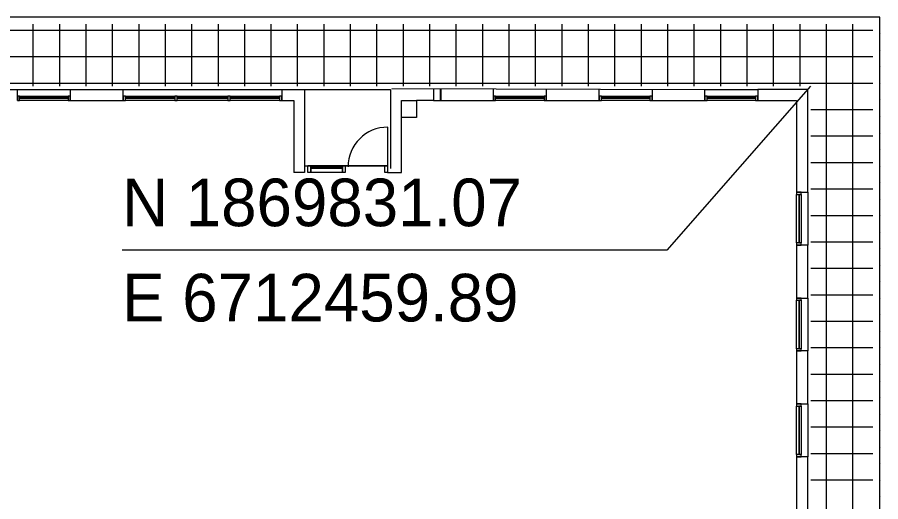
# Model space of a CAD drawing. Extents: x 6712138 to 6712574, y 1869536 to 1870160.
# Drawn here: x 6712399.9 to 6712465.2, y 1869799.7 to 1869836.3 of the extents above; entities that cross this region are included whole.
import ezdxf

# ---------------------------------------------------------------- set-up
doc = ezdxf.new("R2010")
doc.units = 0
for name, color, linetype in [('A-DETL-MBND', 7, 'Continuous'), ('A-FLOR-OTLN', 7, 'Continuous'), ('A-FLOR-PATT', 7, 'Continuous'), ('A-GLAZ', 7, 'Continuous'), ('A-GLAZ-CWMG', 7, 'Continuous'), ('A-GLAZ-FRAM', 7, 'Continuous'), ('A-WALL-FULL-EXT', 7, 'Continuous'), ('I-WALL', 7, 'Continuous')]:
    doc.layers.add(name, color=color, linetype=linetype)

# ---------------------------------------------------------------- blocks, each defined once
blk = doc.blocks.new('Curtain Wall Sgl Glass-WideStiles-PH - Curtain Wall Sgl Glass-187-xAFP01')
at = {"layer": 'A-DETL-MBND'}
blk.add_line((0.0762, 0.0085), (0.0762, 0.1609), dxfattribs=at)
blk.add_arc((0.0762, 0.0085), 0.1524, 90, 180, dxfattribs=at)

msp = doc.modelspace()

# ---------------------------------------------------------------- linework, layer by layer
at = {"layer": 'A-FLOR-OTLN'}
for p, q in [((6712421.62, 1869830.833), (6712428.131, 1869830.833)), ((6712431.391, 1869830.76), (6712431.402, 1869830.76)), ((6712431.933, 1869830.76), (6712431.912, 1869830.76)), ((6712431.391, 1869829.989), (6712431.402, 1869829.989)), ((6712431.912, 1869829.989), (6712431.933, 1869829.989)), ((6712421.62, 1869825.052), (6712427.911, 1869825.052)), ((6712421.891, 1869825.073), (6712427.89, 1869825.073)), ((6712427.89, 1869825.073), (6712427.89, 1869825.098))]:
    msp.add_line(p, q, dxfattribs=at)
msp.add_lwpolyline([(6712463.745, 1869723.291), (6712465.141, 1869723.291), (6712465.141, 1869836.281), (6712254.683, 1869836.281)], dxfattribs=at)
at = {"layer": 'A-FLOR-PATT'}
for p, q in [((6712464.62, 1869835.281), (6712255.204, 1869835.281)), ((6712401.11, 1869831.073), (6712401.11, 1869835.76)), ((6712403.11, 1869831.073), (6712403.11, 1869835.76)), ((6712405.11, 1869831.073), (6712405.11, 1869835.76)), ((6712407.11, 1869831.073), (6712407.11, 1869835.76)), ((6712409.11, 1869831.073), (6712409.11, 1869835.76)), ((6712411.11, 1869831.073), (6712411.11, 1869835.76)), ((6712413.11, 1869831.073), (6712413.11, 1869835.76)), ((6712415.11, 1869831.073), (6712415.11, 1869835.76)), ((6712417.11, 1869831.073), (6712417.11, 1869835.76)), ((6712419.11, 1869831.073), (6712419.11, 1869835.76)), ((6712421.11, 1869831.073), (6712421.11, 1869835.76)), ((6712423.11, 1869831.073), (6712423.11, 1869835.76)), ((6712425.11, 1869831.073), (6712425.11, 1869835.76)), ((6712427.11, 1869831.073), (6712427.11, 1869835.76)), ((6712429.11, 1869831.073), (6712429.11, 1869835.76)), ((6712431.11, 1869831.073), (6712431.11, 1869835.76)), ((6712433.11, 1869831.073), (6712433.11, 1869835.76)), ((6712435.11, 1869831.073), (6712435.11, 1869835.76)), ((6712437.11, 1869831.073), (6712437.11, 1869835.76)), ((6712439.11, 1869831.073), (6712439.11, 1869835.76)), ((6712441.11, 1869831.073), (6712441.11, 1869835.76)), ((6712443.11, 1869831.073), (6712443.11, 1869835.76)), ((6712445.11, 1869831.073), (6712445.11, 1869835.76)), ((6712447.11, 1869831.073), (6712447.11, 1869835.76)), ((6712449.11, 1869831.073), (6712449.11, 1869835.76)), ((6712451.11, 1869831.073), (6712451.11, 1869835.76)), ((6712453.11, 1869831.073), (6712453.11, 1869835.76)), ((6712455.11, 1869831.073), (6712455.11, 1869835.76)), ((6712457.11, 1869831.073), (6712457.11, 1869835.76)), ((6712459.11, 1869831.073), (6712459.11, 1869835.76)), ((6712461.11, 1869759.073), (6712461.11, 1869835.76)), ((6712463.11, 1869759.073), (6712463.11, 1869835.76)), ((6712465.212, 1869835.032), (6712465.212, 1869835.032)), ((6712465.212, 1869833.782), (6712465.212, 1869833.782)), ((6712464.62, 1869833.281), (6712255.204, 1869833.281)), ((6712465.212, 1869832.532), (6712465.212, 1869832.532)), ((6712464.619, 1869831.281), (6712255.204, 1869831.281)), ((6712465.212, 1869831.282), (6712465.212, 1869831.282)), ((6712465.212, 1869830.032), (6712465.212, 1869830.032)), ((6712464.618, 1869829.281), (6712459.933, 1869829.281)), ((6712465.212, 1869828.782), (6712465.212, 1869828.782)), ((6712465.212, 1869827.532), (6712465.212, 1869827.532)), ((6712464.618, 1869827.281), (6712459.933, 1869827.281)), ((6712465.212, 1869826.282), (6712465.212, 1869826.282)), ((6712464.617, 1869825.281), (6712459.933, 1869825.281)), ((6712465.212, 1869825.032), (6712465.212, 1869825.032)), ((6712465.212, 1869823.782), (6712465.212, 1869823.782)), ((6712464.617, 1869823.281), (6712459.933, 1869823.281)), ((6712465.212, 1869822.532), (6712465.212, 1869822.532)), ((6712464.616, 1869821.281), (6712459.933, 1869821.281)), ((6712465.212, 1869821.282), (6712465.212, 1869821.282)), ((6712465.212, 1869820.032), (6712465.212, 1869820.032)), ((6712464.616, 1869819.281), (6712459.933, 1869819.281)), ((6712465.212, 1869818.782), (6712465.212, 1869818.782)), ((6712464.615, 1869817.281), (6712459.933, 1869817.281)), ((6712465.212, 1869817.532), (6712465.212, 1869817.532)), ((6712465.212, 1869816.282), (6712465.212, 1869816.282)), ((6712464.614, 1869815.281), (6712459.933, 1869815.281)), ((6712465.212, 1869815.032), (6712465.212, 1869815.032)), ((6712465.212, 1869813.782), (6712465.212, 1869813.782)), ((6712464.614, 1869813.281), (6712459.933, 1869813.281)), ((6712465.212, 1869812.532), (6712465.212, 1869812.532)), ((6712464.613, 1869811.281), (6712459.933, 1869811.281)), ((6712465.212, 1869811.282), (6712465.212, 1869811.282)), ((6712465.212, 1869810.032), (6712465.212, 1869810.032)), ((6712464.613, 1869809.281), (6712459.933, 1869809.281)), ((6712465.212, 1869808.782), (6712465.212, 1869808.782)), ((6712464.612, 1869807.281), (6712459.933, 1869807.281)), ((6712465.212, 1869807.532), (6712465.212, 1869807.532)), ((6712465.212, 1869806.282), (6712465.212, 1869806.282)), ((6712464.612, 1869805.281), (6712459.933, 1869805.281)), ((6712465.212, 1869805.032), (6712465.212, 1869805.032)), ((6712464.611, 1869803.281), (6712459.933, 1869803.281)), ((6712465.212, 1869803.782), (6712465.212, 1869803.782)), ((6712465.212, 1869802.532), (6712465.212, 1869802.532)), ((6712464.611, 1869801.281), (6712459.933, 1869801.281)), ((6712465.212, 1869801.282), (6712465.212, 1869801.282)), ((6712465.212, 1869800.032), (6712465.212, 1869800.032))]:
    msp.add_line(p, q, dxfattribs=at)
at = {"layer": 'A-GLAZ'}
for p, q in [((6712400.079, 1869830.219), (6712400.079, 1869830.156)), ((6712403.745, 1869830.219), (6712400.079, 1869830.219)), ((6712400.079, 1869830.156), (6712403.745, 1869830.156)), ((6712403.745, 1869830.156), (6712403.745, 1869830.219)), ((6712411.829, 1869830.219), (6712408.079, 1869830.219)), ((6712408.079, 1869830.219), (6712408.079, 1869830.156)), ((6712408.079, 1869830.156), (6712411.829, 1869830.156)), ((6712411.829, 1869830.156), (6712411.829, 1869830.219)), ((6712415.829, 1869830.219), (6712411.995, 1869830.219)), ((6712411.995, 1869830.219), (6712411.995, 1869830.156)), ((6712411.995, 1869830.156), (6712415.829, 1869830.156)), ((6712415.829, 1869830.156), (6712415.829, 1869830.219)), ((6712419.745, 1869830.219), (6712415.995, 1869830.219)), ((6712415.995, 1869830.219), (6712415.995, 1869830.156)), ((6712415.995, 1869830.156), (6712419.745, 1869830.156)), ((6712419.745, 1869830.156), (6712419.745, 1869830.219)), ((6712436.079, 1869830.219), (6712436.079, 1869830.156)), ((6712439.745, 1869830.219), (6712436.079, 1869830.219)), ((6712436.079, 1869830.156), (6712439.745, 1869830.156)), ((6712439.745, 1869830.156), (6712439.745, 1869830.219)), ((6712444.079, 1869830.219), (6712444.079, 1869830.156)), ((6712447.745, 1869830.219), (6712444.079, 1869830.219)), ((6712444.079, 1869830.156), (6712447.745, 1869830.156)), ((6712447.745, 1869830.156), (6712447.745, 1869830.219)), ((6712452.079, 1869830.219), (6712452.079, 1869830.156)), ((6712455.745, 1869830.219), (6712452.079, 1869830.219)), ((6712452.079, 1869830.156), (6712455.745, 1869830.156)), ((6712455.745, 1869830.156), (6712455.745, 1869830.219)), ((6712459.079, 1869822.885), (6712459.016, 1869822.885)), ((6712459.016, 1869822.885), (6712459.016, 1869819.219)), ((6712459.079, 1869819.219), (6712459.079, 1869822.885)), ((6712459.016, 1869819.219), (6712459.079, 1869819.219)), ((6712459.079, 1869814.885), (6712459.016, 1869814.885)), ((6712459.016, 1869814.885), (6712459.016, 1869811.219)), ((6712459.079, 1869811.219), (6712459.079, 1869814.885)), ((6712459.016, 1869811.219), (6712459.079, 1869811.219)), ((6712459.079, 1869806.885), (6712459.016, 1869806.885)), ((6712459.016, 1869806.885), (6712459.016, 1869803.219)), ((6712459.079, 1869803.219), (6712459.079, 1869806.885)), ((6712459.016, 1869803.219), (6712459.079, 1869803.219))]:
    msp.add_line(p, q, dxfattribs=at)
msp.add_lwpolyline([(6712422.099, 1869824.941), (6712424.495, 1869824.941), (6712424.495, 1869824.858), (6712422.099, 1869824.858)], close=True, dxfattribs=at)
at = {"layer": 'A-GLAZ-CWMG'}
for points in [[(6712422.099, 1869824.545), (6712421.891, 1869824.545), (6712421.891, 1869825.045), (6712422.099, 1869825.045)], [(6712424.495, 1869824.545), (6712422.099, 1869824.545), (6712422.099, 1869825.045), (6712424.495, 1869825.045)], [(6712424.704, 1869824.545), (6712424.495, 1869824.545), (6712424.495, 1869825.045), (6712424.704, 1869825.045)], [(6712427.704, 1869825.045), (6712427.912, 1869825.045), (6712427.912, 1869824.545), (6712427.704, 1869824.545)]]:
    msp.add_lwpolyline(points, close=True, dxfattribs=at)
at = {"layer": 'A-GLAZ-FRAM'}
for p, q in [((6712399.912, 1869830.323), (6712399.912, 1869829.989)), ((6712400.079, 1869830.323), (6712399.912, 1869830.323)), ((6712400.079, 1869829.989), (6712400.079, 1869830.323)), ((6712400.079, 1869830.323), (6712403.745, 1869830.323)), ((6712403.745, 1869830.323), (6712403.745, 1869829.989)), ((6712403.912, 1869830.323), (6712403.745, 1869830.323)), ((6712403.912, 1869829.989), (6712403.912, 1869830.323)), ((6712408.079, 1869830.323), (6712407.912, 1869830.323)), ((6712407.912, 1869830.323), (6712407.912, 1869829.989)), ((6712408.079, 1869829.989), (6712408.079, 1869830.323)), ((6712408.079, 1869830.323), (6712411.829, 1869830.323)), ((6712411.995, 1869830.323), (6712411.829, 1869830.323)), ((6712411.829, 1869830.323), (6712411.829, 1869829.989)), ((6712411.995, 1869829.989), (6712411.995, 1869830.323)), ((6712411.995, 1869830.323), (6712415.829, 1869830.323)), ((6712415.995, 1869830.323), (6712415.829, 1869830.323)), ((6712415.829, 1869830.323), (6712415.829, 1869829.989)), ((6712415.995, 1869829.989), (6712415.995, 1869830.323)), ((6712415.995, 1869830.323), (6712419.745, 1869830.323)), ((6712419.912, 1869830.323), (6712419.745, 1869830.323)), ((6712419.745, 1869830.323), (6712419.745, 1869829.989)), ((6712419.912, 1869829.989), (6712419.912, 1869830.323)), ((6712435.912, 1869830.323), (6712435.912, 1869829.989)), ((6712436.079, 1869830.323), (6712435.912, 1869830.323)), ((6712436.079, 1869829.989), (6712436.079, 1869830.323)), ((6712436.079, 1869830.323), (6712439.745, 1869830.323)), ((6712439.745, 1869830.323), (6712439.745, 1869829.989)), ((6712439.912, 1869830.323), (6712439.745, 1869830.323)), ((6712439.912, 1869829.989), (6712439.912, 1869830.323)), ((6712443.912, 1869830.323), (6712443.912, 1869829.989)), ((6712444.079, 1869830.323), (6712443.912, 1869830.323)), ((6712444.079, 1869829.989), (6712444.079, 1869830.323)), ((6712444.079, 1869830.323), (6712447.745, 1869830.323)), ((6712447.745, 1869830.323), (6712447.745, 1869829.989)), ((6712447.912, 1869830.323), (6712447.745, 1869830.323)), ((6712447.912, 1869829.989), (6712447.912, 1869830.323)), ((6712451.912, 1869830.323), (6712451.912, 1869829.989)), ((6712452.079, 1869830.323), (6712451.912, 1869830.323)), ((6712452.079, 1869829.989), (6712452.079, 1869830.323)), ((6712452.079, 1869830.323), (6712455.745, 1869830.323)), ((6712455.745, 1869830.323), (6712455.745, 1869829.989)), ((6712455.912, 1869830.323), (6712455.745, 1869830.323)), ((6712455.912, 1869829.989), (6712455.912, 1869830.323)), ((6712399.912, 1869829.989), (6712400.079, 1869829.989)), ((6712403.745, 1869829.989), (6712400.079, 1869829.989)), ((6712403.745, 1869829.989), (6712403.912, 1869829.989)), ((6712407.912, 1869829.989), (6712408.079, 1869829.989)), ((6712411.829, 1869829.989), (6712408.079, 1869829.989)), ((6712411.829, 1869829.989), (6712411.995, 1869829.989)), ((6712415.829, 1869829.989), (6712411.995, 1869829.989)), ((6712415.829, 1869829.989), (6712415.995, 1869829.989)), ((6712419.745, 1869829.989), (6712415.995, 1869829.989)), ((6712419.745, 1869829.989), (6712419.912, 1869829.989)), ((6712435.912, 1869829.989), (6712436.079, 1869829.989)), ((6712439.745, 1869829.989), (6712436.079, 1869829.989)), ((6712439.745, 1869829.989), (6712439.912, 1869829.989)), ((6712443.912, 1869829.989), (6712444.079, 1869829.989)), ((6712447.745, 1869829.989), (6712444.079, 1869829.989)), ((6712447.745, 1869829.989), (6712447.912, 1869829.989)), ((6712451.912, 1869829.989), (6712452.079, 1869829.989)), ((6712455.745, 1869829.989), (6712452.079, 1869829.989)), ((6712455.745, 1869829.989), (6712455.912, 1869829.989)), ((6712459.183, 1869823.052), (6712458.849, 1869823.052)), ((6712458.849, 1869823.052), (6712458.849, 1869822.885)), ((6712458.849, 1869822.885), (6712459.183, 1869822.885)), ((6712458.849, 1869819.219), (6712458.849, 1869822.885)), ((6712459.183, 1869822.885), (6712459.183, 1869823.052)), ((6712459.183, 1869822.885), (6712459.183, 1869819.219)), ((6712459.183, 1869819.219), (6712458.849, 1869819.219)), ((6712458.849, 1869819.219), (6712458.849, 1869819.052)), ((6712458.849, 1869819.052), (6712459.183, 1869819.052)), ((6712459.183, 1869819.052), (6712459.183, 1869819.219)), ((6712459.183, 1869815.052), (6712458.849, 1869815.052)), ((6712458.849, 1869815.052), (6712458.849, 1869814.885)), ((6712459.183, 1869814.885), (6712459.183, 1869815.052)), ((6712458.849, 1869814.885), (6712459.183, 1869814.885)), ((6712458.849, 1869811.219), (6712458.849, 1869814.885)), ((6712459.183, 1869814.885), (6712459.183, 1869811.219)), ((6712459.183, 1869811.219), (6712458.849, 1869811.219)), ((6712458.849, 1869811.219), (6712458.849, 1869811.052)), ((6712459.183, 1869811.052), (6712459.183, 1869811.219)), ((6712458.849, 1869811.052), (6712459.183, 1869811.052)), ((6712459.183, 1869807.052), (6712458.849, 1869807.052)), ((6712458.849, 1869807.052), (6712458.849, 1869806.885)), ((6712458.849, 1869806.885), (6712459.183, 1869806.885)), ((6712458.849, 1869803.219), (6712458.849, 1869806.885)), ((6712459.183, 1869806.885), (6712459.183, 1869807.052)), ((6712459.183, 1869806.885), (6712459.183, 1869803.219)), ((6712459.183, 1869803.219), (6712458.849, 1869803.219)), ((6712458.849, 1869803.219), (6712458.849, 1869803.052)), ((6712458.849, 1869803.052), (6712459.183, 1869803.052)), ((6712459.183, 1869803.052), (6712459.183, 1869803.219))]:
    msp.add_line(p, q, dxfattribs=at)
at = {"layer": 'A-WALL-FULL-EXT'}
for p, q in [((6712295.745, 1869830.833), (6712421.652, 1869830.833)), ((6712399.912, 1869829.989), (6712399.912, 1869830.833)), ((6712403.912, 1869830.833), (6712403.912, 1869829.989)), ((6712407.912, 1869829.989), (6712407.912, 1869830.833)), ((6712419.912, 1869830.833), (6712419.912, 1869829.989)), ((6712421.62, 1869830.833), (6712421.62, 1869824.545)), ((6712428.131, 1869830.833), (6712428.131, 1869824.858)), ((6712428.245, 1869830.906), (6712451.912, 1869830.833)), ((6712431.391, 1869830.896), (6712431.391, 1869829.989)), ((6712431.402, 1869829.989), (6712431.402, 1869830.896)), ((6712431.912, 1869829.989), (6712431.912, 1869830.895)), ((6712431.933, 1869830.895), (6712431.933, 1869829.989)), ((6712435.912, 1869829.989), (6712435.912, 1869830.882)), ((6712439.912, 1869830.87), (6712439.912, 1869829.989)), ((6712443.912, 1869829.989), (6712443.912, 1869830.858)), ((6712447.912, 1869830.845), (6712447.912, 1869829.989)), ((6712451.912, 1869829.989), (6712451.912, 1869830.833)), ((6712451.912, 1869830.833), (6712455.912, 1869830.833)), ((6712459.693, 1869830.833), (6712455.912, 1869830.833)), ((6712455.912, 1869830.833), (6712455.912, 1869829.989)), ((6712459.693, 1869823.052), (6712459.693, 1869830.833)), ((6712403.912, 1869829.989), (6712407.912, 1869829.989)), ((6712419.912, 1869829.989), (6712420.808, 1869829.989)), ((6712420.808, 1869829.989), (6712420.808, 1869824.545)), ((6712428.974, 1869824.545), (6712428.974, 1869829.989)), ((6712430.662, 1869829.989), (6712430.11, 1869829.989)), ((6712431.391, 1869829.989), (6712430.662, 1869829.989)), ((6712431.402, 1869829.989), (6712431.912, 1869829.989)), ((6712431.933, 1869829.989), (6712435.912, 1869829.989)), ((6712439.912, 1869829.989), (6712443.912, 1869829.989)), ((6712447.912, 1869829.989), (6712451.912, 1869829.989)), ((6712455.912, 1869829.989), (6712458.849, 1869829.989)), ((6712458.849, 1869829.989), (6712458.849, 1869823.052)), ((6712427.891, 1869825.098), (6712427.911, 1869825.098)), ((6712427.911, 1869825.098), (6712427.911, 1869825.052)), ((6712421.62, 1869824.545), (6712420.808, 1869824.545)), ((6712427.912, 1869824.545), (6712428.974, 1869824.545)), ((6712458.849, 1869823.052), (6712459.693, 1869823.052)), ((6712459.693, 1869823.052), (6712459.693, 1869819.052)), ((6712458.849, 1869819.052), (6712458.849, 1869815.052)), ((6712459.693, 1869819.052), (6712458.849, 1869819.052)), ((6712459.693, 1869815.052), (6712459.693, 1869819.052)), ((6712458.849, 1869815.052), (6712459.693, 1869815.052)), ((6712459.693, 1869815.052), (6712459.693, 1869811.052)), ((6712458.849, 1869811.052), (6712458.849, 1869807.052)), ((6712459.693, 1869811.052), (6712458.849, 1869811.052)), ((6712459.693, 1869807.052), (6712459.693, 1869811.052)), ((6712458.849, 1869807.052), (6712459.693, 1869807.052)), ((6712459.693, 1869807.052), (6712459.693, 1869803.052)), ((6712458.849, 1869803.052), (6712458.849, 1869799.052)), ((6712459.693, 1869803.052), (6712458.849, 1869803.052)), ((6712459.693, 1869799.052), (6712459.693, 1869803.052))]:
    msp.add_line(p, q, dxfattribs=at)
msp.add_lwpolyline([(6712428.974, 1869829.989), (6712430.11, 1869829.989), (6712430.11, 1869828.712), (6712428.974, 1869828.712)], close=True, dxfattribs=at)
at = {"layer": 'I-WALL'}
for points in [[(6712459.891, 1869831.073), (6712449.033, 1869818.686)], [(6712449.033, 1869818.686), (6712407.831, 1869818.686)]]:
    msp.add_lwpolyline(points, dxfattribs=at)

# ---------------------------------------------------------------- block references
at = {"layer": 'A-GLAZ', "xscale": 19.68503937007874, "yscale": 19.68503937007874}
msp.add_blockref('Curtain Wall Sgl Glass-WideStiles-PH - Curtain Wall Sgl Glass-187-xAFP01', (6712426.422, 1869824.806), dxfattribs=at)

# ---------------------------------------------------------------- texts
at = {"layer": 'I-WALL'}
for s, p in [('N 1869831.07', (6712407.831, 1869820.486)), ('E 6712459.89', (6712407.831, 1869813.286))]:
    msp.add_text(s, height=3.6, dxfattribs=at).set_placement(p)

doc.saveas('drawing.dxf')
